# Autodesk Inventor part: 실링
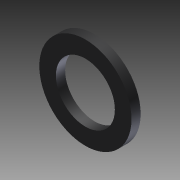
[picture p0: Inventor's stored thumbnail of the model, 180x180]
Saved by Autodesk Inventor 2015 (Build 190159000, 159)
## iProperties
Created: 2024-12
Part Number: 실링
Material: 일반
Document SubType Name: Modeling
Designer: 102566
Density: 1 g/cm^3
Appearance: 기본값
Author: 102566
Author: jhkim
Creation Date: 2024-11-28
Sending System: Autodesk Inventor 2025
Preprocessor: ST-DEVELOPER v20
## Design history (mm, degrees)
node "실링1"
node "솔리드1"
node "기준1"
